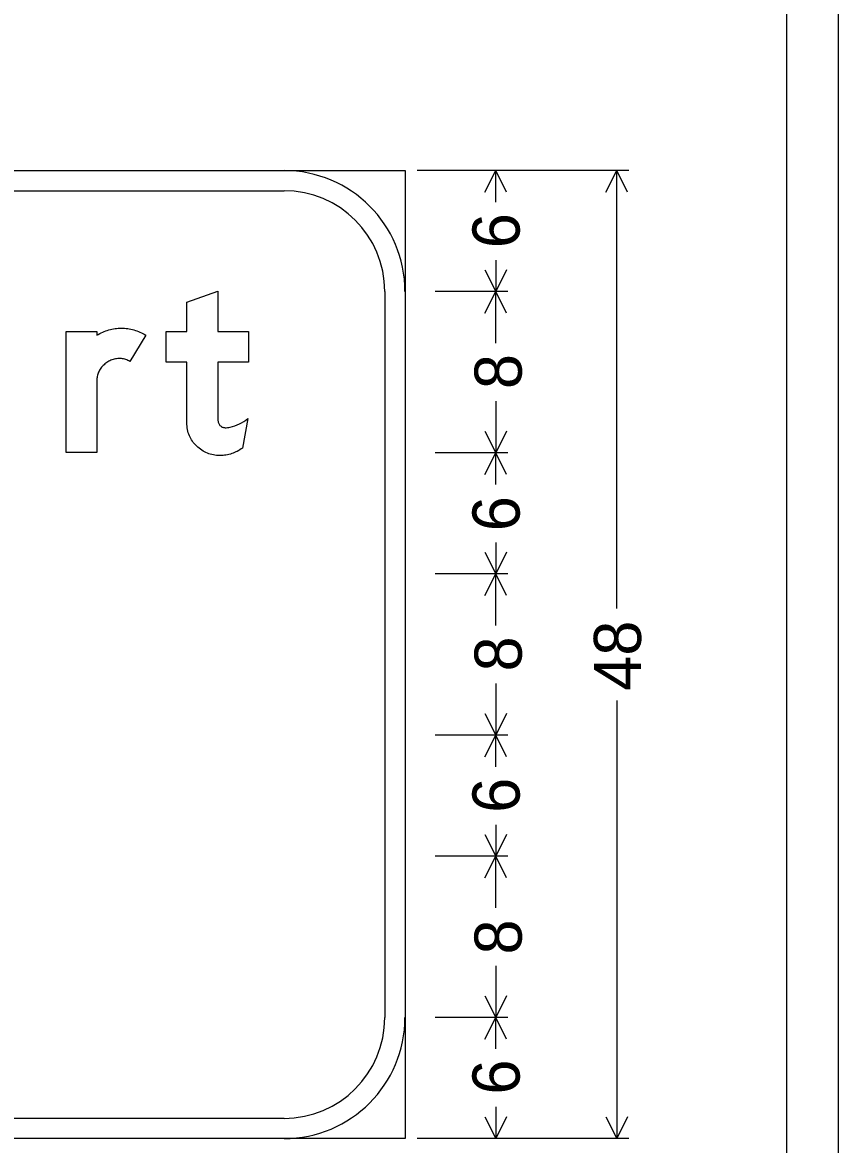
# Model space of a CAD drawing. Extents: x 187716 to 188418, y 178603 to 179533.
# Drawn here: x 188245.1 to 188418.1, y 179057.4 to 179295.2 of the extents above; entities that cross this region are included whole.
import ezdxf

# ---------------------------------------------------------------- set-up
doc = ezdxf.new("R2010")
doc.units = 0
doc.layers.add('Default', color=7, linetype='Continuous')

msp = doc.modelspace()

# ---------------------------------------------------------------- linework, layer by layer
at = {"layer": 'Default'}
for p, q in [((187813.36, 179263.83), (188326.2, 179263.83)), ((187839, 179263.83), (188300.55, 179263.83)), ((188326.2, 179263.83), (188326.2, 179058.69)), ((188373.63, 179263.83), (188328.76, 179263.83)), ((188347.99, 179263.83), (188332.61, 179263.83)), ((188343.13, 179259.24), (188345.43, 179263.83)), ((188345.43, 179257.15), (188345.43, 179263.83)), ((188347.72, 179259.24), (188345.43, 179263.83)), ((188368.77, 179259.24), (188371.07, 179263.83)), ((188371.07, 179170.99), (188371.07, 179263.83)), ((188373.36, 179259.24), (188371.07, 179263.83)), ((187839, 179259.55), (188300.55, 179259.55)), ((188343.13, 179242.77), (188345.43, 179238.18)), ((188345.43, 179244.86), (188345.43, 179238.18)), ((188347.72, 179242.77), (188345.43, 179238.18)), ((188321.92, 179238.18), (188321.92, 179084.33)), ((188326.2, 179238.18), (188326.2, 179084.33)), ((188347.99, 179238.18), (188332.61, 179238.18)), ((188343.13, 179233.6), (188345.43, 179238.18)), ((188345.43, 179227.24), (188345.43, 179238.18)), ((188347.72, 179233.6), (188345.43, 179238.18)), ((188345.43, 179214.94), (188345.43, 179204)), ((188343.13, 179208.58), (188345.43, 179204)), ((188347.72, 179208.58), (188345.43, 179204)), ((188347.99, 179204), (188332.61, 179204)), ((188343.13, 179199.41), (188345.43, 179204)), ((188345.43, 179197.32), (188345.43, 179204)), ((188347.72, 179199.41), (188345.43, 179204)), ((188345.43, 179185.03), (188345.43, 179178.35)), ((188343.13, 179182.94), (188345.43, 179178.35)), ((188347.72, 179182.94), (188345.43, 179178.35)), ((188347.99, 179178.35), (188332.61, 179178.35)), ((188343.13, 179173.77), (188345.43, 179178.35)), ((188345.43, 179167.4), (188345.43, 179178.35)), ((188347.72, 179173.77), (188345.43, 179178.35)), ((188345.43, 179155.11), (188345.43, 179144.16)), ((188371.07, 179151.53), (188371.07, 179058.69)), ((188343.13, 179148.75), (188345.43, 179144.16)), ((188347.72, 179148.75), (188345.43, 179144.16)), ((188347.99, 179144.16), (188332.61, 179144.16)), ((188343.13, 179139.58), (188345.43, 179144.16)), ((188345.43, 179137.49), (188345.43, 179144.16)), ((188347.72, 179139.58), (188345.43, 179144.16)), ((188345.43, 179125.2), (188345.43, 179118.52)), ((188343.13, 179123.11), (188345.43, 179118.52)), ((188347.72, 179123.11), (188345.43, 179118.52)), ((188347.99, 179118.52), (188332.61, 179118.52)), ((188343.13, 179113.94), (188345.43, 179118.52)), ((188345.43, 179107.57), (188345.43, 179118.52)), ((188347.72, 179113.94), (188345.43, 179118.52)), ((188345.43, 179095.28), (188345.43, 179084.33)), ((188343.13, 179088.92), (188345.43, 179084.33)), ((188347.72, 179088.92), (188345.43, 179084.33)), ((188347.99, 179084.33), (188332.61, 179084.33)), ((188347.99, 179084.33), (188332.61, 179084.33)), ((188343.13, 179079.75), (188345.43, 179084.33)), ((188345.43, 179077.66), (188345.43, 179084.33)), ((188347.72, 179079.75), (188345.43, 179084.33)), ((188345.43, 179065.37), (188345.43, 179058.69)), ((188300.55, 179062.96), (187839, 179062.96)), ((188343.13, 179063.28), (188345.43, 179058.69)), ((188347.72, 179063.28), (188345.43, 179058.69)), ((188368.77, 179063.28), (188371.07, 179058.69)), ((188373.36, 179063.28), (188371.07, 179058.69)), ((188326.2, 179058.69), (187813.36, 179058.69)), ((188300.55, 179058.69), (187839, 179058.69)), ((188373.63, 179058.69), (188328.76, 179058.69)), ((188347.99, 179058.69), (188332.61, 179058.69))]:
    msp.add_line(p, q, dxfattribs=at)
for points in [[(188418.09, 178602.69), (188418.09, 179533.02), (187715.97, 179533.02), (187715.97, 178602.69)], [(188407.12, 178613.73), (188407.12, 179522.02), (187727.02, 179522.02), (187727.02, 178613.73)], [(187813.36, 179263.83), (188326.2, 179263.83), (188326.2, 179058.69), (187813.36, 179058.69)]]:
    msp.add_lwpolyline(points, close=True, dxfattribs=at)
for points in [[(188275.6, 179229.7), (188279.98, 179229.7), (188279.98, 179235.92), (188286.5, 179238.29), (188286.5, 179229.7), (188293.01, 179229.7), (188293.01, 179223.25), (188286.5, 179223.25), (188286.5, 179211.06), (188286.53, 179210.87), (188286.56, 179210.68), (188286.61, 179210.5), (188286.66, 179210.35), (188286.73, 179210.19), (188286.8, 179210.06), (188286.89, 179209.93), (188286.98, 179209.81), (188287.08, 179209.71), (188287.2, 179209.62), (188287.32, 179209.54), (188287.45, 179209.47), (188287.6, 179209.42), (188287.74, 179209.38), (188287.91, 179209.35), (188288.08, 179209.33), (188288.31, 179209.32), (188288.57, 179209.35), (188288.84, 179209.39), (188289.14, 179209.46), (188289.65, 179209.59), (188290.15, 179209.75), (188290.63, 179209.93), (188291.11, 179210.14), (188291.57, 179210.38), (188292.03, 179210.65), (188292.47, 179210.94), (188292.91, 179211.26), (188291.78, 179205.01), (188291.5, 179204.82), (188291.22, 179204.64), (188290.94, 179204.48), (188290.65, 179204.32), (188290.36, 179204.18), (188290.07, 179204.06), (188289.77, 179203.94), (188289.48, 179203.83), (188289.18, 179203.74), (188288.87, 179203.66), (188288.56, 179203.59), (188288.25, 179203.54), (188287.94, 179203.5), (188287.62, 179203.47), (188287.3, 179203.45), (188286.97, 179203.44), (188286.62, 179203.45), (188286.27, 179203.47), (188285.92, 179203.51), (188285.58, 179203.56), (188285.25, 179203.64), (188284.93, 179203.72), (188284.61, 179203.82), (188284.3, 179203.94), (188283.99, 179204.07), (188283.69, 179204.21), (188283.4, 179204.38), (188283.11, 179204.56), (188282.83, 179204.75), (188282.56, 179204.96), (188282.3, 179205.18), (188282.04, 179205.42), (188281.78, 179205.67), (188281.55, 179205.93), (188281.33, 179206.2), (188281.13, 179206.47), (188280.95, 179206.75), (188280.78, 179207.04), (188280.63, 179207.34), (188280.49, 179207.64), (188280.37, 179207.95), (188280.27, 179208.27), (188280.18, 179208.6), (188280.1, 179208.93), (188280.05, 179209.27), (188280.01, 179209.62), (188279.98, 179209.98), (188279.98, 179210.34), (188279.98, 179223.25), (188275.6, 179223.25), (188275.6, 179229.7)], [(188254.35, 179229.7), (188260.88, 179229.7), (188260.88, 179228.91), (188261.19, 179229.09), (188261.5, 179229.27), (188261.82, 179229.42), (188262.14, 179229.57), (188262.46, 179229.71), (188262.78, 179229.83), (188263.1, 179229.94), (188263.43, 179230.04), (188263.76, 179230.13), (188264.09, 179230.21), (188264.42, 179230.27), (188264.75, 179230.32), (188265.08, 179230.36), (188265.42, 179230.39), (188265.76, 179230.41), (188266.1, 179230.41), (188266.44, 179230.41), (188266.77, 179230.39), (188267.1, 179230.36), (188267.43, 179230.33), (188267.76, 179230.27), (188268.09, 179230.21), (188268.41, 179230.13), (188268.74, 179230.05), (188269.06, 179229.95), (188269.38, 179229.84), (188269.69, 179229.72), (188270.01, 179229.58), (188270.32, 179229.44), (188270.63, 179229.28), (188270.94, 179229.12), (188271.25, 179228.94), (188267.84, 179223.37), (188267.64, 179223.49), (188267.44, 179223.6), (188267.23, 179223.7), (188267.01, 179223.78), (188266.79, 179223.85), (188266.56, 179223.9), (188266.33, 179223.94), (188266.1, 179223.97), (188265.83, 179223.98), (188265.56, 179223.98), (188265.3, 179223.97), (188265.05, 179223.94), (188264.8, 179223.9), (188264.56, 179223.85), (188264.32, 179223.79), (188264.08, 179223.72), (188263.85, 179223.63), (188263.63, 179223.53), (188263.41, 179223.42), (188263.2, 179223.3), (188262.99, 179223.16), (188262.79, 179223.01), (188262.59, 179222.85), (188262.4, 179222.68), (188262.21, 179222.5), (188262.04, 179222.32), (188261.88, 179222.13), (188261.73, 179221.94), (188261.59, 179221.74), (188261.47, 179221.53), (188261.36, 179221.32), (188261.26, 179221.11), (188261.17, 179220.89), (188261.09, 179220.67), (188261.03, 179220.44), (188260.97, 179220.21), (188260.93, 179219.97), (188260.9, 179219.73), (188260.88, 179219.49), (188260.88, 179219.24), (188260.88, 179204.08), (188254.35, 179204.08), (188254.35, 179229.7)]]:
    msp.add_lwpolyline(points, dxfattribs=at)
for centre, radius, start, end in [((188300.55, 179238.18), 25.64, 0, 90), ((188300.55, 179238.18), 21.37, 0, 90), ((188300.55, 179084.33), 21.37, 270, 0), ((188300.55, 179084.33), 25.64, 270, 0)]:
    msp.add_arc(centre, radius, start, end, dxfattribs=at)

# ---------------------------------------------------------------- texts
for s, p in [('6', (188350.49, 179247.36)), ('8', (188350.93, 179217.51)), ('6', (188350.49, 179187.38)), ('48', (188376.22, 179153.57)), ('8', (188350.93, 179157.67)), ('6', (188350.49, 179127.71)), ('8', (188350.93, 179097.68)), ('6', (188350.49, 179068))]:
    msp.add_text(s, height=10, rotation=90, dxfattribs=at).set_placement(p)

doc.saveas('drawing.dxf')
